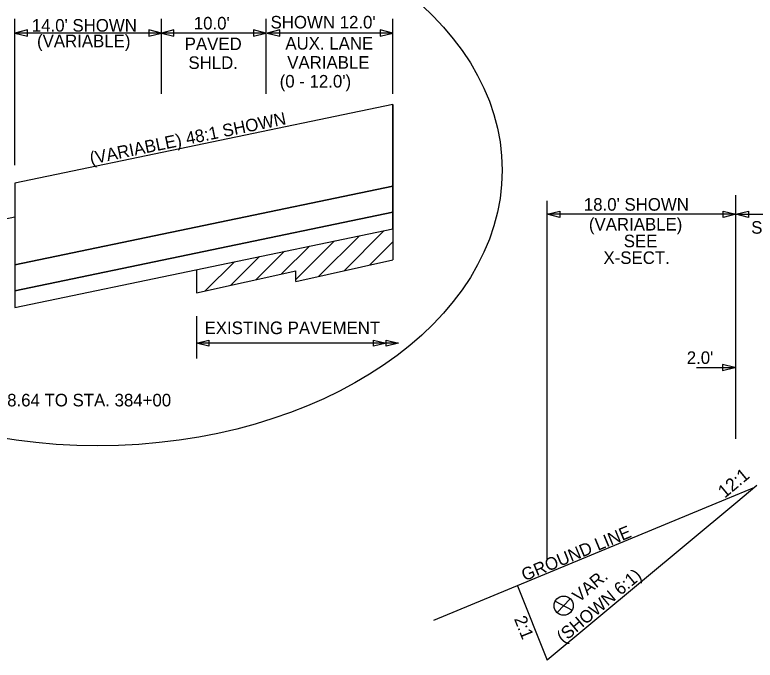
# Model space of a CAD drawing. Extents: x 4832 to 5477, y 4935 to 5220.
# Drawn here: x 5049.2 to 5119.9, y 5066.1 to 5127.7 of the extents above; entities that cross this region are included whole.
import ezdxf

# ---------------------------------------------------------------- set-up
doc = ezdxf.new("R2010")
doc.units = 0
for name, color, linetype in [('RD_QTY_Milling', 7, 'Continuous'), ('RD_QTY_Miscl_1', 7, 'Continuous'), ('RD_QTY_Surf_Course', 7, 'Continuous'), ('RD_SHT_Typical', 7, 'Continuous'), ('RD_TX_TypSect', 7, 'Continuous'), ('RD_XS_ExGround', 7, 'Continuous'), ('RD_XS_ExPaveRet', 7, 'Continuous'), ('RD_XS_PaveShd', 7, 'Continuous'), ('TERMINATOR', 7, 'Continuous')]:
    doc.layers.add(name, color=color, linetype=linetype)

# ---------------------------------------------------------------- blocks, each defined once
blk = doc.blocks.new('AH')
at = {"layer": 'TERMINATOR'}
blk.add_lwpolyline([(-6, 1.5), (0, 0), (-6, -1.5)], close=True, dxfattribs=at)

msp = doc.modelspace()

# ---------------------------------------------------------------- linework, layer by layer
at = {"layer": 'RD_QTY_Milling'}
for p, q in [((5085.297, 5111.347), (5085.297, 5111.347)), ((5085.297, 5111.347), (5085.297, 5111.347)), ((5085.297, 5108.877), (5085.297, 5111.347)), ((5049.216, 5103.826), (5049.216, 5101.356))]:
    msp.add_line(p, q, dxfattribs=at)
for points in [[(5085.297, 5111.347), (5049.216, 5103.826)], [(5049.216, 5101.356), (5085.297, 5108.877)]]:
    msp.add_lwpolyline(points, dxfattribs=at)
at = {"layer": 'RD_QTY_Miscl_1'}
for p, q in [((5085.297, 5108.877), (5049.216, 5101.356)), ((5085.302, 5107.281), (5085.297, 5108.877)), ((5085.297, 5108.877), (5085.297, 5108.877)), ((5049.216, 5099.759), (5085.302, 5107.281)), ((5049.216, 5099.759), (5049.216, 5099.759))]:
    msp.add_line(p, q, dxfattribs=at)
msp.add_lwpolyline([(5049.216, 5101.356), (5049.216, 5099.759)], dxfattribs=at)
at = {"layer": 'RD_SHT_Typical'}
for p, q in [((5049.216, 5103.826), (5049.217, 5099.759)), ((5120.052, 5082.737), (5118.054, 5081.071)), ((5118.054, 5081.071), (5100.045, 5066.063)), ((5097.198, 5073.181), (5100.045, 5066.063))]:
    msp.add_line(p, q, dxfattribs=at)
at = {"layer": 'RD_TX_TypSect'}
for p, q in [((5049.216, 5113.368), (5049.216, 5127.339)), ((5063.21, 5120.156), (5063.21, 5127.339)), ((5073.206, 5120.156), (5073.206, 5127.339)), ((5085.297, 5120.156), (5085.297, 5127.339)), ((5063.21, 5125.966), (5049.216, 5125.966)), ((5073.193, 5125.966), (5063.21, 5125.966)), ((5085.297, 5125.967), (5073.302, 5125.966)), ((5085.302, 5119.154), (5049.216, 5111.633)), ((5085.297, 5111.347), (5085.302, 5119.154)), ((5049.216, 5111.633), (5049.216, 5105.784)), ((5049.216, 5103.826), (5085.297, 5111.347)), ((5085.297, 5111.347), (5085.297, 5111.347)), ((5085.297, 5111.347), (5085.297, 5111.347)), ((5085.297, 5111.347), (5085.297, 5111.347)), ((5118.031, 5087.199), (5118.031, 5110.501)), ((5100.038, 5075.615), (5100.038, 5109.94)), ((5049.216, 5101.356), (5085.297, 5108.877)), ((5118.047, 5108.667), (5100.038, 5108.666)), ((5118.047, 5108.667), (5130.053, 5108.667)), ((5049.217, 5099.759), (5085.302, 5107.281)), ((5049.216, 5105.784), (5049.216, 5103.826)), ((5049.216, 5103.826), (5049.216, 5103.826)), ((5049.216, 5103.826), (5049.216, 5103.826)), ((5066.552, 5098.918), (5066.552, 5094.89)), ((5085.854, 5096.347), (5066.552, 5096.347)), ((5114.281, 5094.027), (5117.958, 5094.027)), ((5100.974, 5070.63), (5102.234, 5071.916)), ((5100.787, 5071.688), (5102.421, 5070.854))]:
    msp.add_line(p, q, dxfattribs=at)
msp.add_lwpolyline([(5049.216, 5103.826), (5085.297, 5111.347)], dxfattribs=at)
msp.add_circle((5101.609, 5071.276), 0.914, dxfattribs=at)
msp.add_ellipse((5057.119, 5112.876), major_axis=(38.618, 0), ratio=0.681891, dxfattribs=at)
at = {"layer": 'RD_XS_ExGround'}
for p, q in [((5117.104, 5081.437), (5119.869, 5082.584)), ((5089.219, 5069.872), (5117.104, 5081.437))]:
    msp.add_line(p, q, dxfattribs=at)
at = {"layer": 'RD_XS_ExPaveRet'}
for p, q in [((5078.215, 5102.724), (5082.106, 5106.615)), ((5080.644, 5103.268), (5084.409, 5107.033)), ((5076.048, 5102.442), (5079.724, 5106.118)), ((5083.074, 5103.813), (5085.302, 5106.041)), ((5072.259, 5102.422), (5074.962, 5105.126)), ((5074.688, 5102.967), (5077.343, 5105.622)), ((5069.829, 5101.878), (5072.581, 5104.629)), ((5067.4, 5101.333), (5070.2, 5104.133)), ((5076.048, 5102.238), (5085.302, 5104.312)), ((5066.552, 5103.373), (5066.552, 5101.143)), ((5066.552, 5101.143), (5076.048, 5103.272)), ((5076.048, 5102.238), (5076.048, 5103.272))]:
    msp.add_line(p, q, dxfattribs=at)
at = {"layer": 'RD_XS_PaveShd'}
for p, q in [((5085.302, 5119.154), (5049.216, 5111.633)), ((5085.302, 5119.154), (5085.302, 5104.301)), ((5049.215, 5111.632), (5049.216, 5103.826)), ((5029.081, 5104.217), (5049.216, 5108.413))]:
    msp.add_line(p, q, dxfattribs=at)

# ---------------------------------------------------------------- block references
at = {"layer": 'RD_QTY_Surf_Course', "xscale": 0.20020004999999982, "yscale": 0.20020004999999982, "rotation": 180}
msp.add_blockref('AH', (5118.047, 5108.667), dxfattribs=at)
at = {"layer": 'TERMINATOR'}
for p, xscale, yscale, rotation in [((5049.216, 5125.966), 0.2000217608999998, -0.20002176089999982, -179.998582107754), ((5063.21, 5125.966), 0.2000217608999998, -0.20002176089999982, 0.0014178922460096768), ((5063.21, 5125.966), 0.2000217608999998, -0.20002176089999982, -179.998582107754), ((5073.302, 5125.966), 0.20002176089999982, -0.20002176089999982, -179.99858211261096), ((5085.297, 5125.967), 0.20002176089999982, -0.20002176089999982, 0.0014178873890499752), ((5100.038, 5108.666), 0.20009999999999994, 0.20009999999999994, -179.99858210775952), ((5118.047, 5108.667), 0.20009999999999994, 0.20009999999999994, 0.0014178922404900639), ((5066.552, 5096.347), 0.1999217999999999, 0.1999217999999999, 180), ((5084.654, 5096.347), 0.2000217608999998, 0.20002176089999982, -0.0014178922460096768), ((5085.854, 5096.347), 0.2000217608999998, 0.20002176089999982, -0.0014178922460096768)]:
    msp.add_blockref('AH', p, dxfattribs=dict(at, xscale=xscale, yscale=yscale, rotation=rotation))
for p, xscale, yscale in [((5073.193, 5125.966), 0.2000217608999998, -0.2000217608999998), ((5117.958, 5094.027), 0.19992179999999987, -0.19992179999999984)]:
    msp.add_blockref('AH', p, dxfattribs=dict(at, xscale=xscale, yscale=yscale))

# ---------------------------------------------------------------- texts
at = {"layer": 'RD_TX_TypSect'}
for s, height, p in [("14.0' SHOWN", 1.2, (5050.842, 5126.107)), ('(VARIABLE)', 1.2, (5051.337, 5124.618)), ('VARIABLE', 1.2, (5075.224, 5122.569)), ("(0 - 12.0')", 1.2, (5074.501, 5120.769)), ('(VARIABLE)', 1.2001, (5104.02, 5107.109)), ('SHOULDER', 1.2001, (5119.51, 5106.806)), ('SEE', 1.2, (5107.347, 5105.513)), ('X-SECT.', 1.2, (5105.411, 5103.916)), ('STA. 366+48.64 TO STA. 384+00', 1.2, (5039.967, 5090.309))]:
    msp.add_text(s, height=height, dxfattribs=at).set_placement(p)
for s, height, rotation, p in [("10.0'", 1.2, 359.99858, (5066.303, 5126.316)), ("SHOWN 12.0'", 1.2, 0.00071, (5073.631, 5126.411)), ('AUX. LANE', 1.2, 359.99858, (5075.045, 5124.398)), ('PAVED', 1.2, 359.99858, (5065.436, 5124.344)), ('SHLD.', 1.2, 359.99858, (5065.79, 5122.547)), ('(VARIABLE) 48:1 SHOWN', 1.2, 11.67599, (5056.501, 5113.405)), ("18.0' SHOWN", 1.20007, 0.00071, (5103.538, 5109.003)), ('EXISTING PAVEMENT', 1.20007, 360, (5067.33, 5097.214)), ("2.0'", 1.2, 359.99858, (5113.361, 5094.367)), ('12:1', 1.2407, 39.80332, (5116.981, 5081.486)), ('GROUND LINE', 1.2, 22.5262, (5097.883, 5073.595)), ('(SHOWN 6:1)', 1.20007, 39.87046, (5101.566, 5067.631)), ('VAR.', 1.2001, 39.87046, (5103.066, 5071.525)), ('2:1', 1.2001, 291.80141, (5096.853, 5070.017))]:
    msp.add_text(s, height=height, rotation=rotation, dxfattribs=at).set_placement(p)

doc.saveas('drawing.dxf')
